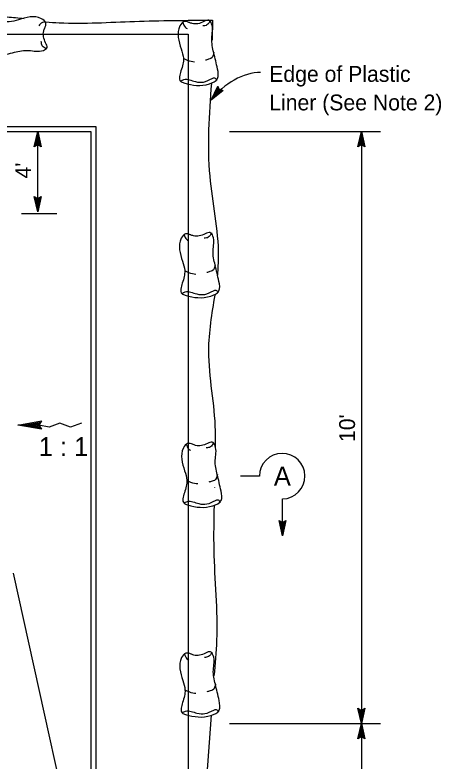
# Model space of a CAD drawing. Extents: x 6708826 to 6711089, y 1868571 to 1869537.
# Drawn here: x 6709144.3 to 6709305.6, y 1868819.1 to 1869101.4 of the extents above; entities that cross this region are included whole.
import ezdxf

# ---------------------------------------------------------------- set-up
doc = ezdxf.new("R2010")
doc.units = 0
for name, color, linetype in [('56 Stg 3 Anno', 7, 'Continuous'), ('57 Undefined', 7, 'Continuous'), ('60 Nongeo Data', 7, 'Continuous')]:
    doc.layers.add(name, color=color, linetype=linetype)

msp = doc.modelspace()

# ---------------------------------------------------------------- linework, layer by layer
at = {"layer": '56 Stg 3 Anno'}
for p, q in [((6709218.56, 1869069.08), (6709221.13, 1869074.39)), ((6709221.13, 1869074.39), (6709221.13, 1869074.39)), ((6709221.13, 1869074.39), (6709221.66, 1869073)), ((6709223.14, 1869072.8), (6709218.56, 1869069.08)), ((6709222.74, 1869072.85), (6709219.38, 1869070.12)), ((6709219.39, 1869070.13), (6709221.26, 1869074)), ((6709220.21, 1869071.16), (6709221.42, 1869073.66)), ((6709222.33, 1869072.89), (6709220.21, 1869071.16)), ((6709221.03, 1869072.2), (6709221.55, 1869073.27)), ((6709221.97, 1869072.96), (6709221.03, 1869072.2)), ((6709221.66, 1869073), (6709223.14, 1869072.8)), ((6709223.14, 1869072.8), (6709223.14, 1869072.8)), ((6709218.56, 1869069.08), (6709218.56, 1869069.08)), ((6709151.64, 1869051.43), (6709152.93, 1869057.19)), ((6709151.64, 1869051.43), (6709152.93, 1869057.19)), ((6709151.98, 1869051.64), (6709152.93, 1869055.87)), ((6709151.98, 1869051.64), (6709152.93, 1869055.87)), ((6709152.33, 1869051.87), (6709152.93, 1869054.54)), ((6709152.33, 1869051.87), (6709152.93, 1869054.54)), ((6709152.93, 1869026.86), (6709152.93, 1869057.19)), ((6709152.93, 1869057.19), (6709152.93, 1869057.19)), ((6709152.93, 1869057.19), (6709154.21, 1869051.43)), ((6709152.93, 1869057.19), (6709152.93, 1869057.19)), ((6709152.93, 1869057.19), (6709154.21, 1869051.43)), ((6709152.93, 1869055.86), (6709153.86, 1869051.66)), ((6709152.93, 1869055.86), (6709153.86, 1869051.66)), ((6709152.93, 1869054.54), (6709153.53, 1869051.83)), ((6709152.93, 1869054.54), (6709153.53, 1869051.83)), ((6709225.55, 1869057.19), (6709282.65, 1869057.19)), ((6709274.16, 1869051.43), (6709275.45, 1869057.19)), ((6709274.5, 1869051.64), (6709275.45, 1869055.87)), ((6709274.85, 1869051.87), (6709275.45, 1869054.54)), ((6709275.45, 1869057.19), (6709275.45, 1868833.28)), ((6709275.45, 1869057.19), (6709275.45, 1869057.19)), ((6709275.45, 1869057.19), (6709276.72, 1869051.43)), ((6709275.45, 1869055.86), (6709276.38, 1869051.66)), ((6709275.45, 1869054.54), (6709276.05, 1869051.83)), ((6709152.93, 1869052.2), (6709151.64, 1869051.43)), ((6709152.93, 1869052.2), (6709151.64, 1869051.43)), ((6709152.66, 1869052.04), (6709152.93, 1869053.22)), ((6709152.66, 1869052.04), (6709152.93, 1869053.22)), ((6709152.93, 1869053.22), (6709153.18, 1869052.05)), ((6709152.93, 1869053.22), (6709153.18, 1869052.05)), ((6709154.21, 1869051.43), (6709152.93, 1869052.2)), ((6709154.21, 1869051.43), (6709152.93, 1869052.2)), ((6709275.45, 1869052.2), (6709274.16, 1869051.43)), ((6709275.18, 1869052.04), (6709275.44, 1869053.22)), ((6709275.44, 1869053.22), (6709275.7, 1869052.05)), ((6709276.72, 1869051.43), (6709275.45, 1869052.2)), ((6709151.64, 1869051.43), (6709151.64, 1869051.43)), ((6709151.64, 1869051.43), (6709151.64, 1869051.43)), ((6709154.21, 1869051.43), (6709154.21, 1869051.43)), ((6709154.21, 1869051.43), (6709154.21, 1869051.43)), ((6709274.16, 1869051.43), (6709274.16, 1869051.43)), ((6709276.72, 1869051.43), (6709276.72, 1869051.43)), ((6709152.93, 1869026.86), (6709151.65, 1869032.62)), ((6709151.65, 1869032.62), (6709151.65, 1869032.62)), ((6709151.65, 1869032.62), (6709152.93, 1869031.86)), ((6709152.93, 1869028.2), (6709152, 1869032.4)), ((6709152.93, 1869029.52), (6709152.33, 1869032.23)), ((6709152.93, 1869030.84), (6709152.67, 1869032)), ((6709152.93, 1869031.86), (6709154.22, 1869032.62)), ((6709154.22, 1869032.62), (6709152.93, 1869026.86)), ((6709153.87, 1869032.42), (6709152.93, 1869028.19)), ((6709153.53, 1869032.19), (6709152.93, 1869029.52)), ((6709153.2, 1869032.02), (6709152.93, 1869030.84)), ((6709154.22, 1869032.62), (6709154.22, 1869032.62)), ((6709146.76, 1869026.26), (6709160.13, 1869026.26)), ((6709152.93, 1869026.86), (6709152.93, 1869026.86)), ((6709145.4, 1868946.17), (6709154.33, 1868947.75)), ((6709147.53, 1868946.17), (6709154.08, 1868947.33)), ((6709154.33, 1868947.75), (6709153.42, 1868946.17)), ((6709154.33, 1868944.6), (6709145.4, 1868946.17)), ((6709154.08, 1868945.01), (6709147.53, 1868946.17)), ((6709149.65, 1868946.17), (6709153.84, 1868946.91)), ((6709153.84, 1868945.44), (6709149.65, 1868946.17)), ((6709151.82, 1868946.17), (6709153.59, 1868946.49)), ((6709153.59, 1868945.86), (6709151.82, 1868946.17)), ((6709153.42, 1868946.17), (6709154.33, 1868944.6)), ((6709236.84, 1868926.88), (6709229.71, 1868926.88)), ((6709245.64, 1868904.33), (6709245.64, 1868918.26)), ((6709245.64, 1868904.33), (6709244.36, 1868910.09)), ((6709244.36, 1868910.09), (6709244.36, 1868910.09)), ((6709244.36, 1868910.09), (6709245.64, 1868909.32)), ((6709245.63, 1868905.66), (6709244.7, 1868909.86)), ((6709245.64, 1868906.98), (6709245.04, 1868909.69)), ((6709245.64, 1868908.31), (6709245.38, 1868909.47)), ((6709245.64, 1868909.32), (6709246.92, 1868910.09)), ((6709246.92, 1868910.09), (6709245.64, 1868904.33)), ((6709246.58, 1868909.88), (6709245.64, 1868905.65)), ((6709246.24, 1868909.66), (6709245.64, 1868906.98)), ((6709245.9, 1868909.49), (6709245.64, 1868908.31)), ((6709246.92, 1868910.09), (6709246.92, 1868910.09)), ((6709245.64, 1868904.33), (6709245.64, 1868904.33)), ((6709275.45, 1868833.28), (6709274.17, 1868839.04)), ((6709274.17, 1868839.04), (6709274.17, 1868839.04)), ((6709274.17, 1868839.04), (6709275.45, 1868838.27)), ((6709275.44, 1868834.61), (6709274.51, 1868838.81)), ((6709275.45, 1868835.93), (6709274.85, 1868838.64)), ((6709275.45, 1868837.26), (6709275.19, 1868838.42)), ((6709275.45, 1868838.27), (6709276.73, 1868839.04)), ((6709276.73, 1868839.04), (6709275.45, 1868833.28)), ((6709276.39, 1868838.83), (6709275.45, 1868834.6)), ((6709276.05, 1868838.61), (6709275.45, 1868835.93)), ((6709275.71, 1868838.44), (6709275.45, 1868837.26)), ((6709276.73, 1868839.04), (6709276.73, 1868839.04)), ((6709225.53, 1868833.28), (6709282.65, 1868833.28)), ((6709274.16, 1868827.52), (6709275.45, 1868833.28)), ((6709274.5, 1868827.73), (6709275.45, 1868831.95)), ((6709275.45, 1868833.28), (6709275.45, 1868756.03)), ((6709275.45, 1868833.28), (6709275.45, 1868833.28)), ((6709275.45, 1868833.28), (6709275.45, 1868833.28)), ((6709275.45, 1868833.28), (6709276.72, 1868827.52)), ((6709275.45, 1868831.94), (6709276.38, 1868827.74)), ((6709274.85, 1868827.95), (6709275.45, 1868830.63)), ((6709275.18, 1868828.12), (6709275.44, 1868829.3)), ((6709275.44, 1868829.3), (6709275.7, 1868828.14)), ((6709275.45, 1868830.63), (6709276.05, 1868827.91)), ((6709275.45, 1868828.29), (6709274.16, 1868827.52)), ((6709274.16, 1868827.52), (6709274.16, 1868827.52)), ((6709276.72, 1868827.52), (6709275.45, 1868828.29)), ((6709276.72, 1868827.52), (6709276.72, 1868827.52))]:
    msp.add_line(p, q, dxfattribs=at)
msp.add_lwpolyline([(6709169.49, 1868946.91), (6709165.4, 1868945.44), (6709161.31, 1868946.91), (6709157.22, 1868945.44), (6709153.42, 1868946.17), (6709145.4, 1868946.17)], dxfattribs=at)
msp.add_arc((6709245.47, 1868926.87), 8.62, 271.113, 179.9585, dxfattribs=at)
msp.add_ellipse((6709230.16, 1869064.46), major_axis=(-14.41, -12.25), ratio=0.619917, start_param=3.775635, end_param=5.024737, dxfattribs=at)
at = {"layer": '60 Nongeo Data'}
for p, q in [((6709219.12, 1869099.36), (6709218.98, 1869091.78)), ((6709219.85, 1868922.53), (6709219.85, 1868922.43)), ((6709218.56, 1868836.41), (6709214.73, 1868784.37))]:
    msp.add_line(p, q, dxfattribs=at)
for points in [[(6708920.45, 1868713.46), (6708920.45, 1869094.08), (6709209.91, 1869094.08), (6709209.91, 1868713.46)], [(6708955.42, 1868754.11), (6708955.42, 1869059.11), (6709174.94, 1869059.11), (6709174.94, 1868765.65)], [(6708957.34, 1868756.03), (6708957.34, 1869057.19), (6709173.02, 1869057.19), (6709173.02, 1868756.03)], [(6709143.66, 1868890.2), (6709172.98, 1868757)]]:
    msp.add_lwpolyline(points, dxfattribs=at)
for points in [[(6709072.66, 1869099.34), (6709108.46, 1869096.89), (6709141.34, 1869100.6), (6709147.79, 1869099.97)], [(6709155.6, 1869096.27), (6709155.99, 1869098.31), (6709154.34, 1869099.91), (6709145.66, 1869099.53), (6709142.1, 1869098.72), (6709137.35, 1869099.67), (6709133.43, 1869099.85), (6709132.81, 1869098.57), (6709132.36, 1869088.97), (6709134.3, 1869085.85), (6709137.92, 1869085.82), (6709144.13, 1869087.21), (6709149.57, 1869087.92), (6709155.08, 1869087.95), (6709156.45, 1869089), (6709155.93, 1869090.82), (6709155.21, 1869095.29), (6709155.68, 1869096.5)], [(6709155.77, 1869098.84), (6709153.8, 1869097.87), (6709153.34, 1869097.2)], [(6709155.99, 1869098.71), (6709161.07, 1869098.41), (6709189.58, 1869098.9), (6709219.07, 1869099.38)], [(6709210.42, 1869098.45), (6709208.38, 1869098.83), (6709206.79, 1869097.17), (6709207.24, 1869088.49), (6709208.08, 1869084.94), (6709207.17, 1869080.18), (6709207.02, 1869076.26), (6709208.3, 1869075.65), (6709217.91, 1869075.28), (6709221.01, 1869077.24), (6709221.01, 1869080.86), (6709219.57, 1869087.05), (6709218.82, 1869092.49), (6709218.74, 1869098), (6709217.68, 1869099.36), (6709215.87, 1869098.83), (6709211.4, 1869098.08), (6709210.19, 1869098.53)], [(6709207.85, 1869098.6), (6709208.83, 1869096.64), (6709209.51, 1869096.19)], [(6709218.21, 1869099.21), (6709217, 1869097.55), (6709215.41, 1869097.17)], [(6709156.29, 1869088.47), (6709154.64, 1869089.7), (6709154.27, 1869091.29)], [(6709219.65, 1869087.13), (6709218.51, 1869084.86), (6709217.61, 1869084.56), (6709216.4, 1869084.19)], [(6709208, 1869084.94), (6709211.03, 1869083.81), (6709212.24, 1869083.66)], [(6709206.94, 1869076.26), (6709208.3, 1869076.94), (6709212.61, 1869076.11), (6709215.64, 1869075.96), (6709218.97, 1869077.31), (6709219.88, 1869077.54), (6709220.71, 1869076.56)], [(6709218.68, 1869075.48), (6709218.04, 1869040.32), (6709221.27, 1869010.15), (6709220.96, 1869002.95)], [(6709210.93, 1869018.14), (6709208.88, 1869018.52), (6709207.3, 1869016.85), (6709207.75, 1869008.17), (6709208.58, 1869004.62), (6709207.67, 1868999.87), (6709207.52, 1868995.94), (6709208.81, 1868995.34), (6709218.42, 1868994.96), (6709221.52, 1868996.92), (6709221.52, 1869000.55), (6709220.08, 1869006.74), (6709219.32, 1869012.17), (6709219.25, 1869017.69), (6709218.19, 1869019.04), (6709216.37, 1869018.52), (6709211.91, 1869017.76), (6709210.7, 1869018.21)], [(6709208.35, 1869018.29), (6709209.34, 1869016.33), (6709210.02, 1869015.87)], [(6709218.72, 1869018.89), (6709217.51, 1869017.23), (6709215.92, 1869016.85)], [(6709220.16, 1869006.81), (6709219.02, 1869004.55), (6709218.11, 1869004.25), (6709216.9, 1869003.87)], [(6709208.51, 1869004.62), (6709211.53, 1869003.49), (6709212.74, 1869003.34)], [(6709207.45, 1868995.94), (6709208.81, 1868996.62), (6709213.12, 1868995.79), (6709216.15, 1868995.64), (6709219.47, 1868997), (6709220.38, 1868997.22), (6709221.21, 1868996.24)], [(6709219.96, 1868995.37), (6709217.58, 1868974.32), (6709220.11, 1868943.98), (6709220.06, 1868937.4)], [(6709211.74, 1868938.83), (6709209.69, 1868939.21), (6709208.1, 1868937.55), (6709208.56, 1868928.87), (6709209.39, 1868925.32), (6709208.48, 1868920.56), (6709208.33, 1868916.63), (6709209.62, 1868916.03), (6709219.23, 1868915.65), (6709222.33, 1868917.62), (6709222.33, 1868921.24), (6709220.89, 1868927.43), (6709220.13, 1868932.87), (6709220.06, 1868938.38), (6709219, 1868939.74), (6709217.18, 1868939.21), (6709212.72, 1868938.45), (6709211.51, 1868938.91)], [(6709209.16, 1868938.98), (6709210.15, 1868937.02), (6709210.83, 1868936.57)], [(6709219.53, 1868939.59), (6709218.32, 1868937.92), (6709216.73, 1868937.55)], [(6709220.97, 1868927.51), (6709219.83, 1868925.24), (6709218.92, 1868924.94), (6709217.71, 1868924.56)], [(6709209.32, 1868925.32), (6709212.34, 1868924.18), (6709213.55, 1868924.03)], [(6709208.26, 1868916.63), (6709209.62, 1868917.31), (6709213.93, 1868916.48), (6709216.96, 1868916.33), (6709220.28, 1868917.69), (6709221.19, 1868917.92), (6709222.02, 1868916.94)], [(6709219.71, 1868915.75), (6709219.58, 1868898.94), (6709220.65, 1868864.76), (6709219.66, 1868851.34)], [(6709211.03, 1868859.52), (6709208.99, 1868859.9), (6709207.4, 1868858.24), (6709207.85, 1868849.56), (6709208.68, 1868846.01), (6709207.78, 1868841.25), (6709207.62, 1868837.33), (6709208.91, 1868836.72), (6709218.52, 1868836.34), (6709221.62, 1868838.31), (6709221.62, 1868841.93), (6709220.18, 1868848.12), (6709219.42, 1868853.56), (6709219.35, 1868859.07), (6709218.29, 1868860.43), (6709216.47, 1868859.9), (6709212.01, 1868859.15), (6709210.8, 1868859.6)], [(6709208.46, 1868859.67), (6709209.44, 1868857.71), (6709210.12, 1868857.26)], [(6709218.82, 1868860.28), (6709217.61, 1868858.62), (6709216.02, 1868858.24)], [(6709208.61, 1868846.01), (6709211.63, 1868844.88), (6709212.84, 1868844.73)], [(6709220.26, 1868848.2), (6709219.12, 1868845.93), (6709218.21, 1868845.63), (6709217, 1868845.25)], [(6709207.55, 1868837.33), (6709208.91, 1868838.01), (6709213.22, 1868837.18), (6709216.25, 1868837.02), (6709219.58, 1868838.38), (6709220.48, 1868838.61), (6709221.32, 1868837.63)]]:
    msp.add_spline(points, degree=3, dxfattribs=at)

# ---------------------------------------------------------------- texts
at = {"layer": '57 Undefined'}
for s, height, p in [('Edge of Plastic', 6, (6709240.57, 1869076.03)), ('Liner (See Note 2)', 6, (6709240.57, 1869065.23)), ('1 : 1', 7.2, (6709153.33, 1868934.43)), ('A', 7.21, (6709242.33, 1868923.27))]:
    msp.add_text(s, height=height, dxfattribs=at).set_placement(p)
for s, p in [("4'", (6709150.41, 1869039.48)), ("10'", (6709273.05, 1868939.78))]:
    msp.add_text(s, height=6, rotation=90, dxfattribs=at).set_placement(p)

doc.saveas('drawing.dxf')
